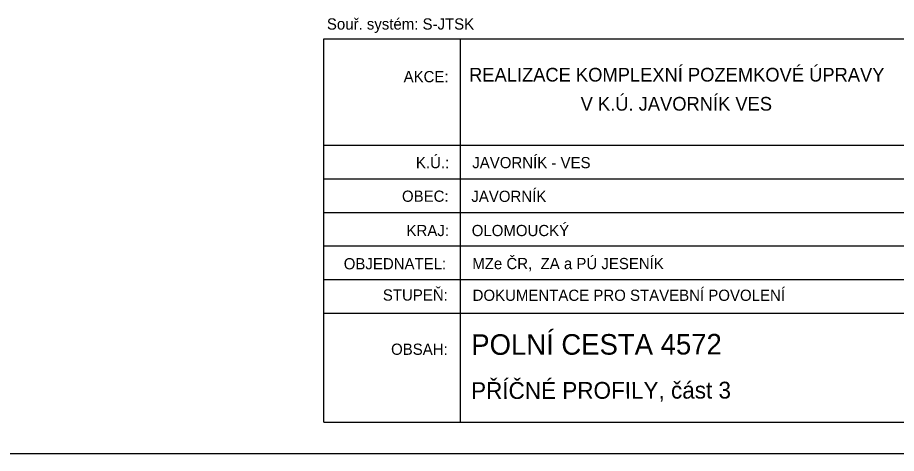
# Model space of a CAD drawing. Extents: x -552501 to -552394, y -1029983 to -1029892.
# Drawn here: x -552436.67 to -552422.56, y -1029982.45 to -1029975.46 of the extents above; entities that cross this region are included whole.
import ezdxf

# ---------------------------------------------------------------- set-up
doc = ezdxf.new("R2010")
doc.units = 0
doc.layers.add('FORMATY', color=7, linetype='Continuous')
doc.layers.add('rámeček', color=7, linetype='Continuous')

msp = doc.modelspace()

# ---------------------------------------------------------------- linework, layer by layer
at = {"layer": 'FORMATY'}
msp.add_line((-552437.755, -1029982.45), (-552435.755, -1029982.45), dxfattribs=at)
at = {"layer": 'rámeček'}
for p, q in [((-552431.755, -1029975.795), (-552416.255, -1029975.795)), ((-552431.755, -1029981.95), (-552431.755, -1029975.795)), ((-552429.562, -1029981.95), (-552429.562, -1029975.795)), ((-552431.755, -1029977.502), (-552416.255, -1029977.502)), ((-552431.755, -1029978.041), (-552416.255, -1029978.041)), ((-552431.755, -1029978.581), (-552416.255, -1029978.581)), ((-552431.755, -1029979.12), (-552416.255, -1029979.12)), ((-552431.755, -1029979.659), (-552416.255, -1029979.659)), ((-552431.755, -1029980.198), (-552417.745, -1029980.198)), ((-552431.755, -1029981.95), (-552416.255, -1029981.95)), ((-552499.755, -1029982.45), (-552415.755, -1029982.45)), ((-552499.755, -1029982.45), (-552415.755, -1029982.45))]:
    msp.add_line(p, q, dxfattribs=at)

# ---------------------------------------------------------------- texts
for s, height, rotation, p in [('Souř. systém: S-JTSK', 0.17971, 0, (-552431.708, -1029975.648)), ('AKCE:', 0.1797, 0, (-552430.476, -1029976.493)), ('REALIZACE KOMPLEXNÍ POZEMKOVÉ ÚPRAVY', 0.22, 0, (-552429.426, -1029976.482)), (' V K.Ú. JAVORNÍK VES', 0.22, 0, (-552427.716, -1029976.949)), ('K.Ú.:', 0.18, 0, (-552430.279, -1029977.873)), ('JAVORNÍK - VES', 0.18, 0, (-552429.374, -1029977.873)), ('OBEC:', 0.18, 0, (-552430.503, -1029978.412)), ('JAVORNÍK', 0.18, 0, (-552429.389, -1029978.414)), ('KRAJ:', 0.18, 0, (-552430.43, -1029978.963)), ('OLOMOUCKÝ', 0.18, 0, (-552429.383, -1029978.963)), ('MZe ČR,  ZA a PÚ JESENÍK', 0.18, 0, (-552429.374, -1029979.493)), ('OBJEDNATEL:', 0.18, 0, (-552431.438, -1029979.496)), ('STUPEŇ:', 0.18, 0, (-552430.81, -1029979.998)), ('DOKUMENTACE PRO STAVEBNÍ POVOLENÍ', 0.18, 0, (-552429.369, -1029980.002)), ('POLNÍ CESTA 4572', 0.33, 0.1038, (-552429.39, -1029980.869)), ('OBSAH:', 0.18, 0, (-552430.678, -1029980.868)), ('PŘÍČNÉ PROFILY, část 3', 0.27, 0.1038, (-552429.393, -1029981.577))]:
    msp.add_text(s, height=height, rotation=rotation, dxfattribs=at).set_placement(p)

doc.saveas('drawing.dxf')
